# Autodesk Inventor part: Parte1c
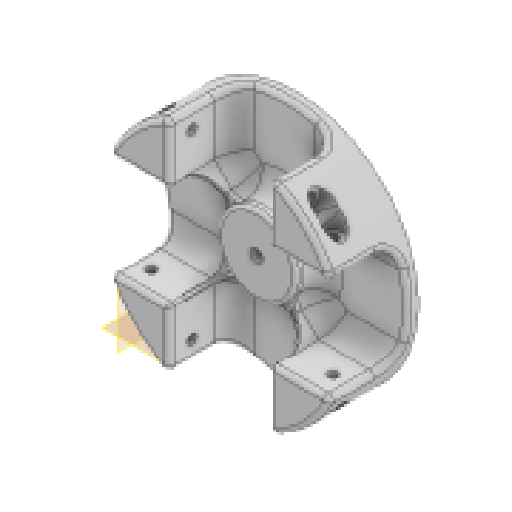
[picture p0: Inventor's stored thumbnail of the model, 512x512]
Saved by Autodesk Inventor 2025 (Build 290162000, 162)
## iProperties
Created: 2025-05
Part Number: Parte1c
Material: Generico
Document SubType Name: Modeling
Designer: R5800u
Density: 1 g/cm^3
Appearance: Default
Author: R5800u
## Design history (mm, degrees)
sketch "Schizzo1" dims "d0" = 100
  geometry: L1 (0, 0)-(35.355, 35.355); L2 (0, 0)-(50, 0); L3 (20.572, 20.572)-(20.572, 45.572); L4 (20.572, 20.572)-(45.572, 20.572); L5 (0, 0)-(0, 44.829) reference; L6 (-20.572, 20.572)-(-20.572, 45.572); L7 (0, 0)-(-35.355, 35.355); L8 (-20.572, 20.572)-(-45.572, 20.572); L9 (0, 0)-(56.569, 0); L10 (26.572, 42.355)-(26.572, 26.572); L11 (26.572, 26.572)-(42.355, 26.572); L12 (-26.572, 42.355)-(-26.572, 26.572); L13 (-26.572, 26.572)-(-42.355, 26.572); L14 (-20.572, 24.815)-(0, 4.243); L15 (0, 4.243)-(20.572, 24.815); L16 (24.815, 20.572)-(0, -4.243); L17 (0, -4.243)-(-24.815, 20.572); L18 (20.572, -20.572)-(20.572, -45.572); L19 (0, -4.243)-(20.572, -24.815); L20 (26.572, -42.355)-(26.572, -26.572); L21 (24.815, -20.572)-(0, 4.243); L22 (0, 0)-(35.355, -35.355); L23 (26.572, -26.572)-(42.355, -26.572); L24 (20.572, -20.572)-(45.572, -20.572); L25 (0, 0)-(0, -44.829); L26 (-20.572, -24.815)-(0, -4.243); L27 (0, 4.243)-(-24.815, -20.572); L28 (0, 0)-(-35.355, -35.355); L29 (-20.572, -20.572)-(-20.572, -45.572); L30 (-26.572, -42.355)-(-26.572, -26.572); L31 (-26.572, -26.572)-(-42.355, -26.572); L32 (-20.572, -20.572)-(-45.572, -20.572); 3 further points
  constraints: 64 end point, 25 symmetric about line, 13 point on line, 3 vertical, 2 coincident, 2 horizontal, 1 equal length, 9 other
  dimensions: "d1" = 45 deg angle of L2 L1; "d3" = 25 distance of L3.start L4.end; "d8" = 6 distance between parallel lines of L3 L10; "d9" = 6 distance between parallel lines of L6 L12; "d10" = 3 distance between parallel lines of L7 L14; "d11" = 3 distance between parallel lines of L1 L16; "d22" = 6 distance between parallel lines of L4 L11; "d23" = 6 distance between parallel lines of L8 L13
extrude "Estrusione1" new body sketch "Schizzo1" stored distance "d4" = 75; taper "d5" = 0 deg
node "Piano di lavoro1"
sketch "Schizzo3" dims "d24" = 100
  geometry: L1 (0, 0)-(35.355, 35.355); L2 (0, 0)-(50, 0); L3 (20.572, 20.572)-(20.572, 45.572); L4 (20.572, 20.572)-(45.572, 20.572); L5 (0, 0)-(0, 44.829); L6 (-20.572, 20.572)-(-20.572, 45.572); L7 (0, 0)-(-35.355, 35.355); L8 (-20.572, 20.572)-(-45.572, 20.572); L9 (0, 0)-(56.569, 0); L10 (26.572, 42.355)-(26.572, 26.572); L11 (26.572, 26.572)-(42.355, 26.572); L12 (-26.572, 42.355)-(-26.572, 26.572); L13 (-26.572, 26.572)-(-42.355, 26.572); L14 (-20.572, 24.815)-(0, 4.243); L15 (0, 4.243)-(20.572, 24.815); L16 (24.815, 20.572)-(0, -4.243); L17 (0, -4.243)-(-24.815, 20.572); L18 (20.572, -20.572)-(20.572, -45.572); L19 (0, -4.243)-(20.572, -24.815); L20 (26.572, -42.355)-(26.572, -26.572); L21 (24.815, -20.572)-(0, 4.243); L22 (0, 0)-(35.355, -35.355); L23 (26.572, -26.572)-(42.355, -26.572); L24 (20.572, -20.572)-(45.572, -20.572); L25 (0, 0)-(0, -44.829); L26 (-20.572, -24.815)-(0, -4.243); L27 (0, 4.243)-(-24.815, -20.572); L28 (0, 0)-(-35.355, -35.355); L29 (-20.572, -20.572)-(-20.572, -45.572); L30 (-26.572, -42.355)-(-26.572, -26.572); L31 (-26.572, -26.572)-(-42.355, -26.572); L32 (-20.572, -20.572)-(-45.572, -20.572); 16 further points
  constraints: 64 end point, 25 symmetric about line, 13 point on line, 2 coincident, 2 horizontal, 2 parallel, 2 vertical, 1 equal length, 9 other
  dimensions: "d25" = 45 deg angle of L2 L1; "d26" = 25 distance of L3.start L4.end; "d27" = 6 distance between parallel lines of L3 L10; "d28" = 6 distance between parallel lines of L6 L12; "d29" = 3 distance between parallel lines of L7 L14; "d30" = 3 distance between parallel lines of L1 L16; "d31" = 6 distance between parallel lines of L4 L11; "d32" = 6 distance between parallel lines of L8 L13; "d41" = 3 distance between parallel lines of L1 L15; "d42" = 3 distance between parallel lines of L7 L17; "d63" = 25 distance of L18.start L24.end (derived); "d64" = 25 distance of L18.start L18.end (derived); "d65" = 41.14378 distance between parallel lines of L32 L8 (derived); "d66" = 41.14378 distance between parallel lines of L24 L4 (derived); "d67" = 41.14378 distance between parallel lines of L3 L6 (derived); "d68" = 41.14378 distance between parallel lines of L18 L29 (derived)
extrude "Estrusione4" cut sketch "Schizzo3" extent not by distance; stored distance "d33" = 30; taper "d34" = 0 deg
sketch "Schizzo4"
  geometry: L1 (45.572, 37.5)-(45.572, 3) reference; L2 (45.572, 20.25)-(0, 20.25); L3 (0, 3)-(0, 37.5) reference; C1 r 2 at (37, 20.25); 2 further points
  constraints: 2 end point, 2 midpoint, 1 centre point, 1 coincident, 1 point on line
  dimensions: "d36" = 37 horizontal distance of point (0, 0) point (37, 20.25); "d37" = 4 diameter of C1
extrude "Estrusione5" cut sketch "Schizzo4" extent not by distance; stored distance "d38" = 0; taper "d39" = 0 deg
pattern_circular "Serie circolare1" dims angle "d47" = 360 deg
sketch "Schizzo5"
  geometry: C1 r 50 at (0, 0) reference; 1 further point
extrude "Estrusione6" cut sketch "Schizzo5" distance "d53" = 36; taper "d54" = 0 deg
sketch "Schizzo6"
  geometry: L1 (45.572, -20.572)-(20.572, -20.572) reference; L2 (20.572, 20.572)-(45.572, 20.572) reference; L3 (20.572, 45.572)-(20.572, 20.572) reference; L4 (-20.572, 20.572)-(-20.572, 45.572) reference; L5 (-45.572, 20.572)-(-20.572, 20.572) reference; L6 (-20.572, -20.572)-(-45.572, -20.572) reference; L7 (-20.572, -45.572)-(-20.572, -20.572) reference; L8 (20.572, -20.572)-(20.572, -45.572) reference; L9 (-20.572, 24.815)-(-24.815, 20.572); L10 (-24.815, 20.572)-(-20.572, 24.815); L11 (-24.815, -20.572)-(-20.572, -24.815); L12 (20.572, 24.815)-(24.815, 20.572); L13 (24.815, -20.572)-(20.572, -24.815); C1 r 16 at (0, 0); A1 r 50 centre (0, 0) between (45.572, 20.572) and (20.572, 45.572) reference; A2 r 50 centre (0, 0) between (-20.572, 45.572) and (-45.572, 20.572) reference; A3 r 50 centre (0, 0) between (-45.572, -20.572) and (-20.572, -45.572) reference; A4 r 50 centre (0, 0) between (20.572, -45.572) and (45.572, -20.572) reference; A5 r 35 centre (0, 53.131) between (-20.572, 24.815) and (20.572, 24.815); A6 r 35 centre (-53.131, 0) between (-24.815, -20.572) and (-24.815, 20.572); A7 r 35 centre (0, -53.131) between (20.572, -24.815) and (-20.572, -24.815); A8 r 35 centre (53.131, 0) between (24.815, 20.572) and (24.815, -20.572); 1 further point
  constraints: 10 end point, 8 point on circle, 5 centre point, 1 coincident, 1 parallel, 1 perpendicular, 17 other
  dimensions: "d55" = 32 diameter of C1; "d109" = 35 radius of A5; "d112" = 360 deg dimension on point (0, 0) A5.centre (derived)
extrude "Estrusione7" join sketch "Schizzo6" stored distance "d56" = 36; taper "d57" = 0 deg
sketch "Schizzo7"
  geometry: C1 r 2.5 at (0, 0); 1 further point
  constraints: 1 centre point, 1 coincident
  dimensions: "d69" = 5 diameter of C1
extrude "Estrusione8" cut sketch "Schizzo7" extent not by distance; stored distance "d70" = 10; taper "d71" = 0 deg
sketch "Schizzo8"
  geometry: L1 (20.572, 20.572)-(45.572, 20.572) reference; L2 (20.572, 45.572)-(20.572, 20.572) reference; L3 (-20.572, 20.572)-(-20.572, 45.572) reference; L4 (-45.572, 20.572)-(-20.572, 20.572) reference; L5 (-20.572, -20.572)-(-45.572, -20.572) reference; L6 (-20.572, -45.572)-(-20.572, -20.572) reference; L7 (20.572, -20.572)-(20.572, -45.572) reference; L8 (45.572, -20.572)-(20.572, -20.572) reference; A1 r 50 centre (0, 0) between (45.572, 20.572) and (20.572, 45.572) reference; A2 r 50 centre (0, 0) between (20.572, -45.572) and (45.572, -20.572) reference; A3 r 50 centre (0, 0) between (-45.572, -20.572) and (-20.572, -45.572) reference; A4 r 50 centre (0, 0) between (-20.572, 45.572) and (-45.572, 20.572) reference; A5 r 35 centre (0, 53.131) between (-20.572, 24.815) and (20.572, 24.815); A6 r 35 centre (-53.131, 0) between (-24.815, -20.572) and (-24.815, 20.572); A7 r 35 centre (0, -53.131) between (20.572, -24.815) and (-20.572, -24.815); A8 r 35 centre (53.131, 0) between (24.815, 20.572) and (24.815, -20.572); 9 further points
  constraints: 8 point on circle, 4 centre point, 17 other
  dimensions: "d104" = 35 radius of A5; "d107" = 360 deg dimension on point (0, 0) A5.centre (derived)
extrude "Estrusione9" cut sketch "Schizzo8" distance "d72" = 8; taper "d73" = 0 deg
node "Piano di lavoro3"
sketch "Schizzo10"
  geometry: C1 r 2 at (-17.25, 8.572) reference; C2 r 4.25 at (-17.25, 8.572); 1 further point
  constraints: 1 centre point, 1 coincident
  dimensions: "d86" = 8.5 diameter of C2
extrude "Estrusione11" cut sketch "Schizzo10" distance "d87" = 13; taper "d88" = 0 deg
node "Piano di lavoro4"
sketch "Schizzo11"
  geometry: C1 r 2 at (8.572, -17.25) reference; C2 r 4.25 at (8.572, -17.25); 1 further point
  constraints: 1 centre point, 1 coincident
  dimensions: "d90" = 8.5 diameter of C2
extrude "Estrusione12" cut sketch "Schizzo11" distance "d91" = 13; taper "d92" = 0 deg
pattern_circular "Serie circolare4" dims "d94" = 360 deg
sketch "Schizzo12"
  geometry: C1 r 2.5 at (0, 0) reference; C2 r 6 at (0, 0); 1 further point
  constraints: 1 centre point, 1 coincident
  dimensions: "d128" = 12 diameter of C2
extrude "Estrusione13" cut sketch "Schizzo12" distance "d129" = 13; taper "d130" = 0 deg
sketch "Schizzo14"
  geometry: C1 r 6 at (0, 0) reference; C2 r 16 at (0, 0) reference; C3 r 2.5 at (0, 0) reference; C4 r 20 at (0, 0); 1 further point
  constraints: 1 centre point, 1 coincident
  dimensions: "d133" = 40 diameter of C4
extrude "Estrusione14" cut sketch "Schizzo14" distance "d131" = 15; taper "d132" = 0 deg
sketch "Schizzo17"
  geometry: L1 (-45.572, -20.572)-(-20.572, -20.572) reference; L2 (-20.572, -20.572)-(-20.572, -45.572) reference; L3 (20.572, -45.572)-(20.572, -20.572) reference; L4 (20.572, -20.572)-(45.572, -20.572) reference; L5 (45.572, 20.572)-(20.572, 20.572) reference; L6 (20.572, 20.572)-(20.572, 45.572) reference; L7 (-20.572, 45.572)-(-20.572, 20.572) reference; L8 (-20.572, 20.572)-(-45.572, 20.572) reference; L9 (20.572, 20.572)-(0, 0); L10 (21.986, 20.572)-(0.707, -0.707); L11 (20.572, 21.986)-(-0.707, 0.707); C1 r 16 at (0, 0) reference; C2 r 2.5 at (0, 0) reference; A1 r 50 centre (0, 0) between (-20.572, -45.572) and (20.572, -45.572) reference; A2 r 50 centre (0, 0) between (45.572, -20.572) and (45.572, 20.572) reference; A3 r 50 centre (0, 0) between (20.572, 45.572) and (-20.572, 45.572) reference; A4 r 50 centre (0, 0) between (-45.572, 20.572) and (-45.572, -20.572) reference; 3 further points
  constraints: 6 end point, 2 parallel, 2 point on line
  dimensions: "d149" = 1 distance between parallel lines of L9 L10; "d150" = 1 distance between parallel lines of L9 L11
extrude "Estrusione16" join sketch "Schizzo17" distance "d151" = 10; taper "d152" = 0 deg
pattern_circular "Serie circolare9" dims angle "d154" = 360 deg
fillet "Raccordo32" dims "d164" = 8
fillet "Raccordo33" dims "d165" = 9.9
fillet "Raccordo34" dims "d166" = 2
fillet "Raccordo35" dims "d167" = 2
fillet "Raccordo36" dims "d168" = 1
fillet "Raccordo37" dims "d169" = 1.5
fillet "Raccordo38" dims "d170" = 3
fillet "Raccordo39" dims "d171" = 5
feature "ڽ耀ڿ耀ہ耀ۃ耀ۅ耀ۇ耀ۉ耀ۋ耀" dims "d0" = 100, "d1" = 45 deg, "d3" = 25, "d4" = 75, "d5" = 0, "d8" = 6, "d9" = 6, "d10" = 3, "d11" = 3, "d12" = 3, "d18" = 2, "d19" = 2, "d22" = 6, "d23" = 6, "d24" = 100, "d25" = 45 deg, "d26" = 25, "d27" = 6, "d28" = 6, "d29" = 3, "d30" = 3, "d31" = 6, "d32" = 6, "d33" = 30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
node "Solido1"
node "Linea chiusa proiettata1"
node "Schizzo - Serie circolare1" dims "d107" = 360 deg (derived)
node "Linea chiusa proiettata2"
node "Schizzo - Serie circolare2" dims "d112" = 360 deg (derived)
node "Linea chiusa proiettata3"
node "Linea chiusa proiettata4"
